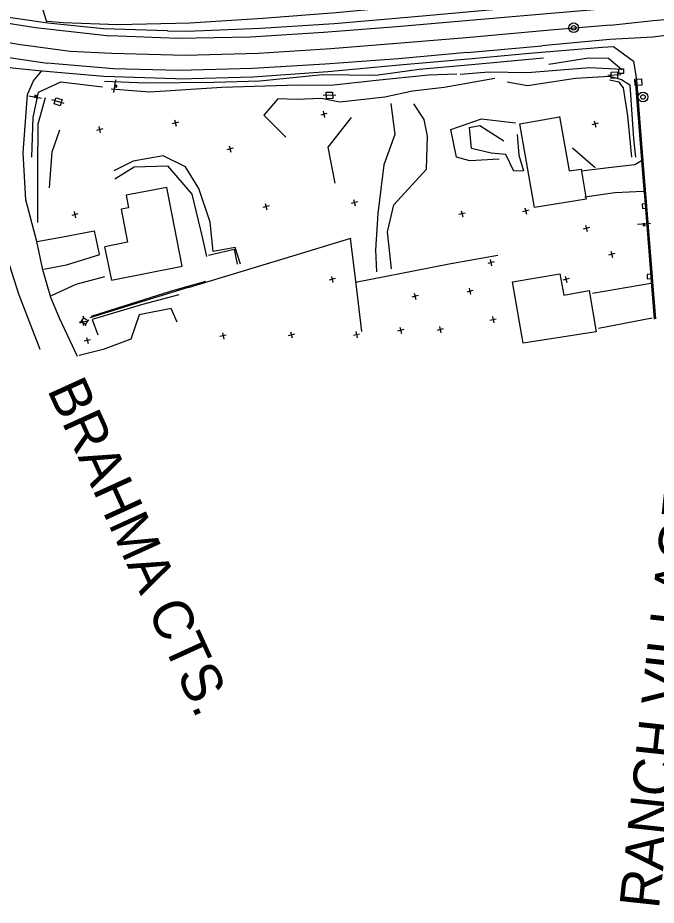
# Model space of a CAD drawing. Extents: x 4711259 to 4716401, y 890074 to 892728.
# Drawn here: x 4715293 to 4715789, y 890547 to 891237 of the extents above; entities that cross this region are included whole.
import ezdxf

# ---------------------------------------------------------------- set-up
doc = ezdxf.new("R2010")
doc.units = 0
for name, color, linetype in [('E_HY_STORM_Inlet', 7, 'Continuous'), ('E_HY_STORM_MH', 7, 'Continuous'), ('E_RDWY_PHOTOG_Eave', 7, 'Continuous'), ('E_RDWY_PHOTOG_Fence', 7, 'Continuous'), ('E_RDWY_ROAD_Approach', 7, 'Continuous'), ('E_RDWY_ROAD_Bikeway', 7, 'Continuous'), ('E_RDWY_ROAD_Curb', 7, 'Continuous'), ('E_RDWY_ROAD_EdgeAsph', 7, 'Continuous'), ('E_RDWY_ROAD_EdgeGravel', 7, 'Continuous'), ('E_RDWY_ROAD_Mailbox', 7, 'Continuous'), ('E_RDWY_ROAD_NameTx', 7, 'Continuous'), ('E_RDWY_ROAD_Striping', 7, 'Continuous'), ('E_RDWY_ROAD_TBofCurb', 7, 'Continuous'), ('E_TERR_DTM_BrkLines', 7, 'Continuous'), ('E_TERR_DTM_RandomPt', 7, 'Continuous'), ('E_TRAF_SIGN_PublicSign', 7, 'Continuous'), ('E_UTIL_COMM_General', 7, 'Continuous'), ('E_UTIL_ELEC_POLE', 7, 'Continuous'), ('E_UTIL_WTR_General', 7, 'Continuous')]:
    doc.layers.add(name, color=color, linetype=linetype)

msp = doc.modelspace()

# ---------------------------------------------------------------- linework, layer by layer
at = {"layer": 'E_HY_STORM_Inlet'}
msp.add_line((4715775.35, 891186.79), (4715775.35, 891186.79), dxfattribs=at)
msp.add_lwpolyline([(4715773, 891184.15), (4715772.71, 891189.14), (4715777.7, 891189.43), (4715777.99, 891184.44)], close=True, dxfattribs=at)
at = {"layer": 'E_HY_STORM_MH'}
for centre, radius in [((4715725.1, 891229.13), 3.75), ((4715725.1, 891229.13), 1.76), ((4715779, 891175.34), 3.75), ((4715779, 891175.34), 1.76)]:
    msp.add_circle(centre, radius, dxfattribs=at)
at = {"layer": 'E_RDWY_PHOTOG_Eave'}
for points in [[(4715714.05, 891160.06), (4715721.61, 891118.08), (4715731.04, 891119.29), (4715734.91, 891096.03), (4715694.58, 891089.4), (4715683.32, 891154.43), (4715714.08, 891160.03)], [(4715360.8, 891058.96), (4715366.07, 891032.89), (4715421.07, 891043.97), (4715409.05, 891105.04), (4715377.52, 891099.06), (4715379.37, 891089.31), (4715373.7, 891088.1), (4715378.57, 891062.41), (4715360.89, 891058.95)], [(4715714.33, 891037.99), (4715717.43, 891021.27), (4715737.16, 891024.91), (4715742.59, 890992.87), (4715685.88, 890984.1), (4715677.51, 891031.58), (4715714.36, 891037.85)]]:
    msp.add_lwpolyline(points, dxfattribs=at)
at = {"layer": 'E_RDWY_PHOTOG_Fence'}
for points in [[(4715560.46, 890993.13), (4715555.8, 891032.1), (4715551.72, 891065.52), (4715551.73, 891065.26), (4715500.64, 891049.75), (4715426.39, 891027.4), (4715425.69, 891027.23), (4715386.1, 891015.2), (4715349.23, 891003.6)], [(4715555.77, 891031.55), (4715613.84, 891042.74), (4715630.98, 891046.28), (4715631.38, 891046.15), (4715666.31, 891052.52)]]:
    msp.add_lwpolyline(points, dxfattribs=at)
at = {"layer": 'E_RDWY_ROAD_Approach'}
for points in [[(4715777.72, 891125.83), (4715772.73, 891122.67), (4715752.25, 891120.35), (4715731.27, 891117.76)], [(4715733.68, 891097.73), (4715757.09, 891101.15), (4715779.39, 891102.15)], [(4715356.89, 891052.65), (4715330.97, 891044.64), (4715313.58, 891041.27)], [(4715319.5, 891021.01), (4715338.79, 891029.8), (4715361, 891035.88)], [(4715739.72, 891023.01), (4715785.13, 891030.67)], [(4715417.02, 891000.36), (4715412.43, 891010.9), (4715387.67, 891006.1), (4715381.14, 890987.03), (4715359.68, 890979.13), (4715341.08, 890974.57)], [(4715786.14, 891003.37), (4715744.36, 890995.47)]]:
    msp.add_lwpolyline(points, dxfattribs=at)
at = {"layer": 'E_RDWY_ROAD_Bikeway'}
msp.add_lwpolyline([(4715761.78, 891260.06), (4715760.61, 891260.12), (4715718.68, 891256.93), (4715663.31, 891252.09), (4715598.39, 891246.08), (4715540.62, 891240.77), (4715483.75, 891236.34), (4715426.99, 891232.63), (4715370.72, 891231.33), (4715328.5, 891232.91), (4715316.43, 891233.99)], dxfattribs=at)
at = {"layer": 'E_RDWY_ROAD_Curb'}
msp.add_lwpolyline([(4715773.85, 891188.6), (4715779.1, 891122.44), (4715780.65, 891103.4), (4715786.12, 891035.65), (4715786.42, 891031.6), (4715788.63, 891003.05)], dxfattribs=at)
at = {"layer": 'E_RDWY_ROAD_EdgeAsph'}
for points in [[(4715315.77, 891233.57), (4715312.94, 891242.69), (4715313.46, 891256.68), (4715312.87, 891274.28), (4715310.83, 891294.38), (4715301.47, 891336.28), (4715297.58, 891365.21), (4715298.06, 891377.67), (4715306.35, 891414.08), (4715315.97, 891445.5), (4715326.54, 891475.87), (4715333.43, 891497.68)], [(4715409.6, 891226.77), (4715359.83, 891228.29), (4715316.67, 891232.81), (4715271.74, 891239.12), (4715218.49, 891250.62), (4715160.24, 891265.73), (4715104.58, 891282.25)], [(4715096.24, 891247.13), (4715163.63, 891227.31), (4715218.72, 891213.48), (4715266.26, 891202.31), (4715288.92, 891198.06), (4715312.27, 891195.56), (4715360.18, 891191.53), (4715415.92, 891189.63)], [(4715409.6, 891226.77), (4715425.01, 891226.45), (4715481.8, 891228.87), (4715539.04, 891232.52), (4715595.96, 891237.39), (4715662.3, 891243.21)], [(4715646.34, 891205.25), (4715690.92, 891209.51), (4715747.14, 891214.01), (4715755.95, 891214.53), (4715771.59, 891203.09), (4715773.85, 891188.6)], [(4715415.92, 891189.63), (4715418.72, 891189.54), (4715475.81, 891191.07), (4715534.17, 891195.23), (4715589.88, 891200.29), (4715646.34, 891205.25)], [(4715266.87, 891201.96), (4715277.92, 891185.17), (4715274.97, 891161.65), (4715274.24, 891132.31), (4715275.61, 891096.31), (4715280.13, 891065.65), (4715293.87, 891022.27), (4715310.35, 890979.37)], [(4715339.83, 890973.63), (4715325.82, 891003.45), (4715319.02, 891019.62), (4715312.82, 891040.95), (4715308.18, 891062.94), (4715299.59, 891095.29), (4715297.46, 891131.87), (4715300.77, 891177.28), (4715305.43, 891187.88), (4715312.09, 891195.58)]]:
    msp.add_lwpolyline(points, dxfattribs=at)
at = {"layer": 'E_RDWY_ROAD_EdgeGravel'}
for points in [[(4715304.3, 891128.6), (4715305.4, 891159.4), (4715309.31, 891179.08), (4715326.8, 891187.18), (4715359.02, 891183.12)], [(4715308.18, 891062.94), (4715326.98, 891066.28), (4715352.72, 891071.4), (4715356.52, 891053.21)]]:
    msp.add_lwpolyline(points, dxfattribs=at)
at = {"layer": 'E_RDWY_ROAD_Mailbox'}
for points in [[(4715782.04, 891089.03), (4715781.68, 891092.51), (4715778.19, 891092.15), (4715778.56, 891088.67)], [(4715785.83, 891034.28), (4715785.58, 891037.77), (4715782.09, 891037.52), (4715782.33, 891034.03)]]:
    msp.add_lwpolyline(points, close=True, dxfattribs=at)
at = {"layer": 'E_RDWY_ROAD_Striping'}
for points in [[(4715747.32, 891243.49), (4715701.5, 891239.6), (4715644.11, 891234.72), (4715587.74, 891229.82), (4715530.75, 891225.39), (4715474.19, 891221.81), (4715417.61, 891220.88), (4715364.79, 891222.96)], [(4715753.79, 891231.19), (4715707.16, 891227.31), (4715641.73, 891221.35), (4715594.15, 891217.33), (4715536.6, 891212.83), (4715480.27, 891209.02), (4715423.41, 891207.6), (4715366.26, 891209.06), (4715334.05, 891210.8)], [(4715753.16, 891220.13), (4715700.34, 891215.05)], [(4715642.43, 891209.96), (4715589.13, 891205.12), (4715532.12, 891200.82), (4715475.59, 891197.37), (4715418.36, 891195.84), (4715367.57, 891197.26), (4715316.17, 891201.6)], [(4715642.43, 891209.96), (4715700.34, 891215.05)]]:
    msp.add_lwpolyline(points, dxfattribs=at)
at = {"layer": 'E_RDWY_ROAD_TBofCurb'}
msp.add_lwpolyline([(4715787.96, 891002.69), (4715785.64, 891031.57), (4715785.26, 891035.71), (4715780.35, 891098.49), (4715779.91, 891103.28), (4715778.34, 891122.28), (4715778.04, 891126.31), (4715773.1, 891188.54)], dxfattribs=at)
at = {"layer": 'E_TERR_DTM_BrkLines'}
for points in [[(4715266.29, 891235.81), (4715306.97, 891229.33), (4715364.79, 891222.96)], [(4715753.79, 891231.19), (4715786.85, 891234.87), (4715808.61, 891236.7)], [(4715820.97, 891226.18), (4715786.72, 891221.93), (4715753.16, 891220.13)], [(4715334.05, 891210.8), (4715293.69, 891216.07), (4715270.84, 891220.22)], [(4715267.2, 891208.86), (4715316.06, 891201.56)], [(4715701.62, 891205.55), (4715645.78, 891200.22), (4715604.99, 891196.77), (4715571.55, 891192.13), (4715529.98, 891192.52), (4715481.46, 891187.71), (4715445.93, 891186.51), (4715392.82, 891186.2), (4715360.7, 891187.39)], [(4715705.94, 891200.89), (4715736.51, 891205.88), (4715752.28, 891205.41), (4715762.43, 891196.7), (4715737.55, 891197.89), (4715689.28, 891194.1), (4715659.33, 891194.59), (4715637.03, 891192.82)], [(4715365.98, 891181.63), (4715395.83, 891179.31), (4715451.85, 891183.02), (4715510.71, 891184.81), (4715536.37, 891184.65), (4715571.78, 891188.45), (4715612.35, 891192.58), (4715634.44, 891193.28)], [(4715663.86, 891189.67), (4715624.56, 891182.65), (4715599.91, 891179.8), (4715578.45, 891175.28), (4715543.38, 891171.26), (4715529.32, 891174.28), (4715509.45, 891173.42), (4715495.25, 891173.88), (4715484.55, 891161.15), (4715501.52, 891143.99)], [(4715673.4, 891187.06), (4715689.21, 891184.15), (4715726.47, 891189.91), (4715752.86, 891191.62), (4715762.19, 891189), (4715768.74, 891184.77), (4715771.7, 891142.94), (4715773.24, 891128.7)], [(4715770.22, 891128.66), (4715767.1, 891160.73), (4715763.74, 891182.4), (4715760.44, 891186.97), (4715752.99, 891188.54)], [(4715308.86, 891077.8), (4715308.93, 891118.91), (4715309.28, 891154.47), (4715314.79, 891174.9)], [(4715583.04, 891170.31), (4715586.08, 891146.3), (4715577.76, 891122.52), (4715573, 891084.81), (4715571.18, 891056.62), (4715571.84, 891039.54)], [(4715583.68, 891041.8), (4715580.52, 891070.68), (4715585.51, 891091.62), (4715610.83, 891119.18), (4715611.63, 891144.81), (4715609.07, 891157.92), (4715600.91, 891169.99)], [(4715552.27, 891159.5), (4715534.24, 891136.23), (4715539.62, 891108.43)], [(4715667.37, 891126.91), (4715644.56, 891125.84), (4715634.01, 891128.54), (4715629.75, 891150.07), (4715653.53, 891158.4), (4715679.81, 891155.2)], [(4715318.07, 891104.78), (4715320.08, 891132.63), (4715326.1, 891149.85)], [(4715681.21, 891146.07), (4715682.46, 891130.01), (4715686.21, 891118.01), (4715678.64, 891117.8), (4715672.37, 891130.68), (4715661.01, 891131.61), (4715645.73, 891135.36), (4715644.23, 891151.65), (4715652.24, 891153.21), (4715670.91, 891141.21)], [(4715741.83, 891120.36), (4715724.27, 891135.47)], [(4715466.21, 891045.37), (4715462.22, 891058.28), (4715445.2, 891055.39), (4715442.85, 891077.98), (4715434.02, 891104.11), (4715423.48, 891121.01), (4715406.38, 891129.64), (4715383.04, 891125.57), (4715367.85, 891117.97)], [(4715368.62, 891111.7), (4715383.75, 891120.96), (4715409.52, 891121.89), (4715428.56, 891099.79), (4715436.78, 891065.28), (4715439.9, 891051.26)], [(4715441.4, 891052.35), (4715461.52, 891057.16), (4715463.83, 891045.42)], [(4715350.49, 891004.99), (4715411.88, 891024.56), (4715439.43, 891032.34)], [(4715418.55, 891021.72), (4715390.25, 891014.1), (4715351.11, 891002.55), (4715355.43, 890990.5)]]:
    msp.add_lwpolyline(points, dxfattribs=at)
at = {"layer": 'E_TERR_DTM_RandomPt'}
for p, q in [((4715533.48, 891162.57), (4715528.63, 891161.34)), ((4715530.44, 891164.38), (4715531.67, 891159.53)), ((4715418.08, 891155.79), (4715413.23, 891154.56)), ((4715415.04, 891157.6), (4715416.27, 891152.75)), ((4715744.13, 891154.92), (4715739.29, 891153.69)), ((4715741.09, 891156.72), (4715742.32, 891151.88)), ((4715359.26, 891150.51), (4715354.38, 891149.42)), ((4715356.27, 891152.41), (4715357.36, 891147.53)), ((4715460.57, 891135.53), (4715455.72, 891134.3)), ((4715457.53, 891137.34), (4715458.76, 891132.49)), ((4715485.47, 891092.48), (4715486.7, 891087.63)), ((4715557.13, 891093.77), (4715552.28, 891092.54)), ((4715554.09, 891095.58), (4715555.32, 891090.73)), ((4715337.07, 891086.31), (4715338.16, 891081.43)), ((4715488.51, 891090.67), (4715483.67, 891089.44)), ((4715640.76, 891085.16), (4715635.91, 891083.93)), ((4715637.72, 891086.97), (4715638.95, 891082.12)), ((4715690.24, 891087.33), (4715685.39, 891086.1)), ((4715687.2, 891089.13), (4715688.43, 891084.29)), ((4715340.06, 891084.42), (4715335.18, 891083.33)), ((4715737.32, 891073.86), (4715732.47, 891072.63)), ((4715734.28, 891075.67), (4715735.51, 891070.82)), ((4715757.03, 891053.6), (4715752.19, 891052.37)), ((4715753.99, 891055.4), (4715755.22, 891050.56)), ((4715663.25, 891047.14), (4715658.37, 891046.05)), ((4715660.27, 891049.03), (4715661.36, 891044.15)), ((4715539.95, 891034.16), (4715535.11, 891032.93)), ((4715536.92, 891035.96), (4715538.15, 891031.12)), ((4715721.53, 891034.2), (4715716.69, 891032.97)), ((4715718.49, 891036.01), (4715719.72, 891031.16)), ((4715646.9, 891024.94), (4715642.05, 891023.71)), ((4715643.86, 891026.75), (4715645.09, 891021.9)), ((4715604.31, 891020.97), (4715599.46, 891019.74)), ((4715601.27, 891022.77), (4715602.5, 891017.93)), ((4715343.09, 891002.58), (4715344.32, 890997.73)), ((4715664.93, 891002.76), (4715660.05, 891001.67)), ((4715661.95, 891004.65), (4715663.04, 890999.77)), ((4715346.13, 891000.77), (4715341.28, 890999.54)), ((4715590.1, 890996.46), (4715591.33, 890991.62)), ((4715620.81, 890996.92), (4715622.04, 890992.07)), ((4715455.25, 890990.21), (4715450.37, 890989.12)), ((4715452.27, 890992.11), (4715453.36, 890987.23)), ((4715508.16, 890991.09), (4715503.31, 890989.86)), ((4715505.12, 890992.9), (4715506.35, 890988.06)), ((4715558.85, 890991.14), (4715553.97, 890990.05)), ((4715555.87, 890993.04), (4715556.96, 890988.16)), ((4715593.14, 890994.65), (4715588.29, 890993.43)), ((4715623.85, 890995.11), (4715619, 890993.88)), ((4715349.83, 890986.69), (4715344.98, 890985.46)), ((4715346.79, 890988.5), (4715348.02, 890983.65))]:
    msp.add_line(p, q, dxfattribs=at)
at = {"layer": 'E_TRAF_SIGN_PublicSign'}
for p, q in [((4715368.05, 891178.91), (4715369.53, 891188.8)), ((4715369.53, 891183.74), (4715369.53, 891183.74)), ((4715311.86, 891174.24), (4715302.01, 891175.99)), ((4715307.07, 891175.86), (4715307.07, 891175.86)), ((4715774.76, 891076.51), (4715784.73, 891077.26)), ((4715779.8, 891076.14), (4715779.8, 891076.14))]:
    msp.add_line(p, q, dxfattribs=at)
for points in [[(4715368.68, 891183.11), (4715370.16, 891182.89), (4715370.39, 891184.38), (4715368.9, 891184.6)], [(4715307.67, 891174.99), (4715307.94, 891176.46), (4715306.46, 891176.72), (4715306.2, 891175.25)], [(4715778.99, 891076.83), (4715779.11, 891075.33), (4715780.6, 891075.45), (4715780.49, 891076.94)]]:
    msp.add_lwpolyline(points, close=True, dxfattribs=at)
at = {"layer": 'E_UTIL_COMM_General'}
msp.add_lwpolyline([(4715763.7, 891193.59), (4715760.2, 891193.64), (4715760.25, 891197.14), (4715763.75, 891197.09)], close=True, dxfattribs=at)
at = {"layer": 'E_UTIL_ELEC_POLE'}
for p, q in [((4715761.69, 891192.43), (4715751.69, 891192.12)), ((4715540.5, 891176.78), (4715530.51, 891176.37)), ((4715329.39, 891170.17), (4715319.83, 891173.11))]:
    msp.add_line(p, q, dxfattribs=at)
for points in [[(4715759.27, 891189.86), (4715754.27, 891189.7), (4715754.11, 891194.7), (4715759.11, 891194.85)], [(4715538.1, 891174.18), (4715533.11, 891173.97), (4715532.9, 891178.97), (4715537.9, 891179.17)], [(4715326.27, 891168.52), (4715321.49, 891169.98), (4715322.96, 891174.76), (4715327.74, 891173.29)]]:
    msp.add_lwpolyline(points, close=True, dxfattribs=at)
at = {"layer": 'E_UTIL_WTR_General'}
for p, q in [((4715344.51, 891003.75), (4715344.24, 891004.9)), ((4715342.52, 891000.57), (4715341.38, 891000.31)), ((4715345.7, 890998.59), (4715345.97, 890997.44)), ((4715347.69, 891001.77), (4715348.84, 891002.04))]:
    msp.add_line(p, q, dxfattribs=at)
msp.add_lwpolyline([(4715344.51, 891003.75), (4715347.69, 891001.77), (4715345.7, 890998.59), (4715342.52, 891000.57)], close=True, dxfattribs=at)

# ---------------------------------------------------------------- texts
at = {"layer": 'E_RDWY_ROAD_NameTx'}
for s, rotation, p in [('BRAHMA CTS.', 294.4903, (4715315.87, 890947.88)), ('RANCH VILLAGE', 83.83149, (4715791.25, 890543.87))]:
    msp.add_text(s, height=30.8399, rotation=rotation, dxfattribs=at).set_placement(p)

doc.saveas('drawing.dxf')
